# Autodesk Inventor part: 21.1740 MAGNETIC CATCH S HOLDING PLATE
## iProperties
Created: 2007-03
Part Number: 21.1740 MAGNETIC CATCH S HOLDING PLATE
Material: Steel
Document SubType Name: Modeling
Designer: Andy Moles
Mass: 6.94381 g
Surface Area: 8.21693 cm^2
Volume: 0.884562 cm^3
Density: 7.85 g/cm^3
Author: Andy Moles
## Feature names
1. Base1
